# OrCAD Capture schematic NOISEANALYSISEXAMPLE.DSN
size A; title: Audio Filter and Amplifier; rev: A; company: EMA Design Automation; note: EMA-12345678; note: 225 Tech Park Dr; note: Rochester, NY, 14623
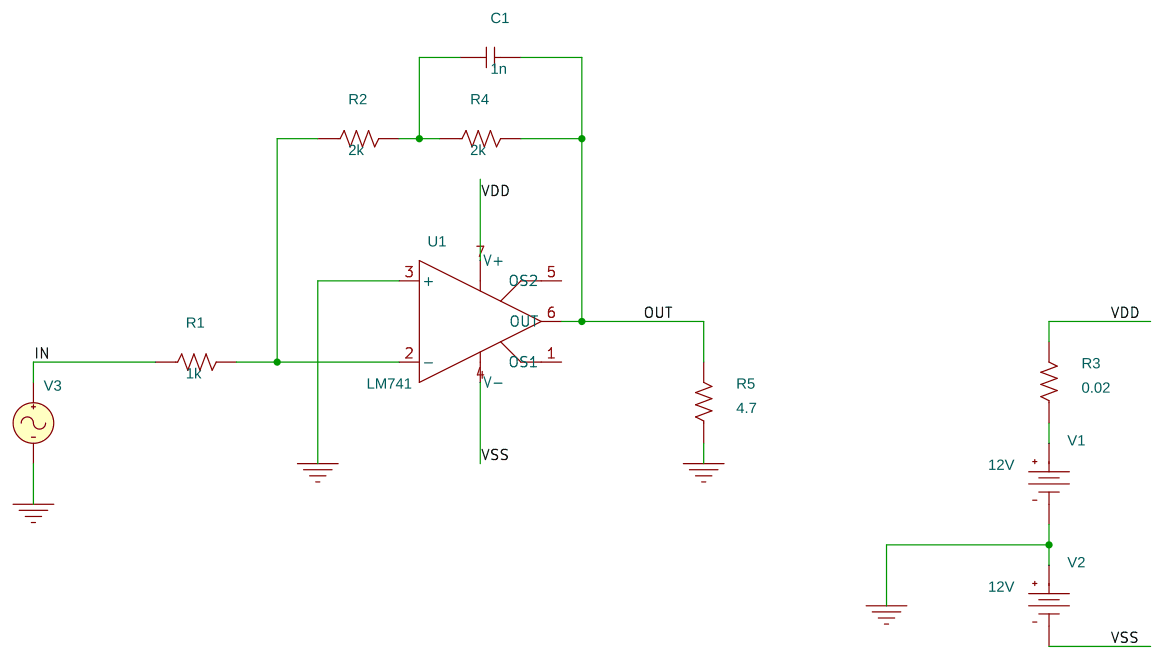
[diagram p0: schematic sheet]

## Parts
C1  1n  [cap196]
R1  1k  [AXRC05]
R2  2k  [AXRC05]
R3  0.02  [AXRC05]
R4  2k  [AXRC05]
R5  4.7  [AXRC05]
U1  LM741  [DIP1008W300L450]
V1  VDC
V2  VDC
V3  VAC

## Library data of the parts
C1 = C
R1-R5 = R
U1 = LM741
V1 V2 = VDC: DC: 12V
V3 = VAC

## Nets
VDD: R3.2 U1.7(V+)
VSS: U1.4(V-) V2.1(-)
0: R5.1 U1.3(+) V1.1(-) V2.0(+) V3.2(-)
IN: R1.1 V3.1(+)
OUT: C1.2 R4.2 R5.2 U1.6(OUT)
N00343: R1.2 R2.1 U1.2(-)
N00435: R3.1 V1.0(+)
N00583: C1.1 R2.2 R4.1

Not connected (* = marked no-connect by the designer): U1 1(OS1) 5(OS2)
